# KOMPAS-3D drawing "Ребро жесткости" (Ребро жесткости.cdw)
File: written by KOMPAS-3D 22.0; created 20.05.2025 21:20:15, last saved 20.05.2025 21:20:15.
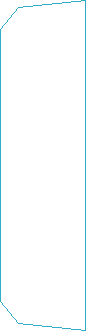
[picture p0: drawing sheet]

Sheet 1: A4, portrait

Document properties: Автор: TC; Масса: 0.212744; Полное имя файла: Ребро жесткости.m3d

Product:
- Part/product: Ребро жесткости
    Масса: 0.212744

Title block, sheet 1: Наименование: Ребро жесткости; Материал: Сталь 10 ГОСТ 1050-2013; Масса: 0,21; Количество листов документа: 1; Форматы листов документа: A4

Views: Проекционный вид 2
Referenced files in D:\Работа\2025\5. Май\Задание №6 - Тележка для крыши\3Д\Рама направляющих\: Ребро жесткости.m3d
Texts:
  Без оформления
Dimensions and other numbers on the sheet: 1:1; 1; 0,21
